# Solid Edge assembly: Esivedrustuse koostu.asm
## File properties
Author: Türk
Template: Iso Assembly.asm
Last saved by: Türk
Revision: 26
Application: Solid Edge
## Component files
Hoidja.par
Liigend1.par
Polt80x20.par
Mutter.par
si.par
Poldikoostu2.asm
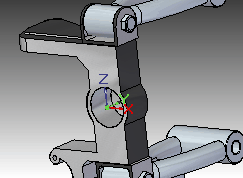
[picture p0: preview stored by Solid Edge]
